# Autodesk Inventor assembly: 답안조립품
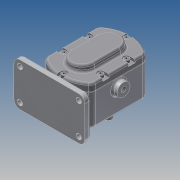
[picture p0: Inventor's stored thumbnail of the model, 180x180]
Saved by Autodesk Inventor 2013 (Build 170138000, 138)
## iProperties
Created: 2019-03
Part Number: 답안조립품
Document SubType Name: Assembly
Designer: Administrator
Author: Administrator
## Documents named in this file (11)
- C:\Users\Administrator\Desktop\490307V1027\답안조립품.iam
- C:\Users\Administrator\Desktop\490307V1027\개스킷.ipt
- C:\Users\Administrator\Desktop\490307V1027\메인축.ipt
- C:\Users\Administrator\Desktop\490307V1027\베어링부시.ipt
- C:\Users\Administrator\Desktop\490307V1027\본체.ipt
- C:\Users\Administrator\Desktop\490307V1027\볼트 M5.ipt
- C:\Users\Administrator\Desktop\490307V1027\서브축.ipt
- C:\Users\Administrator\Desktop\490307V1027\스퍼기어.ipt
- C:\Users\Administrator\Desktop\490307V1027\오일 실 16 28 7.ipt
- C:\Users\Administrator\Desktop\490307V1027\커버.ipt
- C:\Users\Administrator\Desktop\490307V1027\키 6 x 6 x 18.ipt
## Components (1 placed, 1 different names)
1. 개스킷:1
